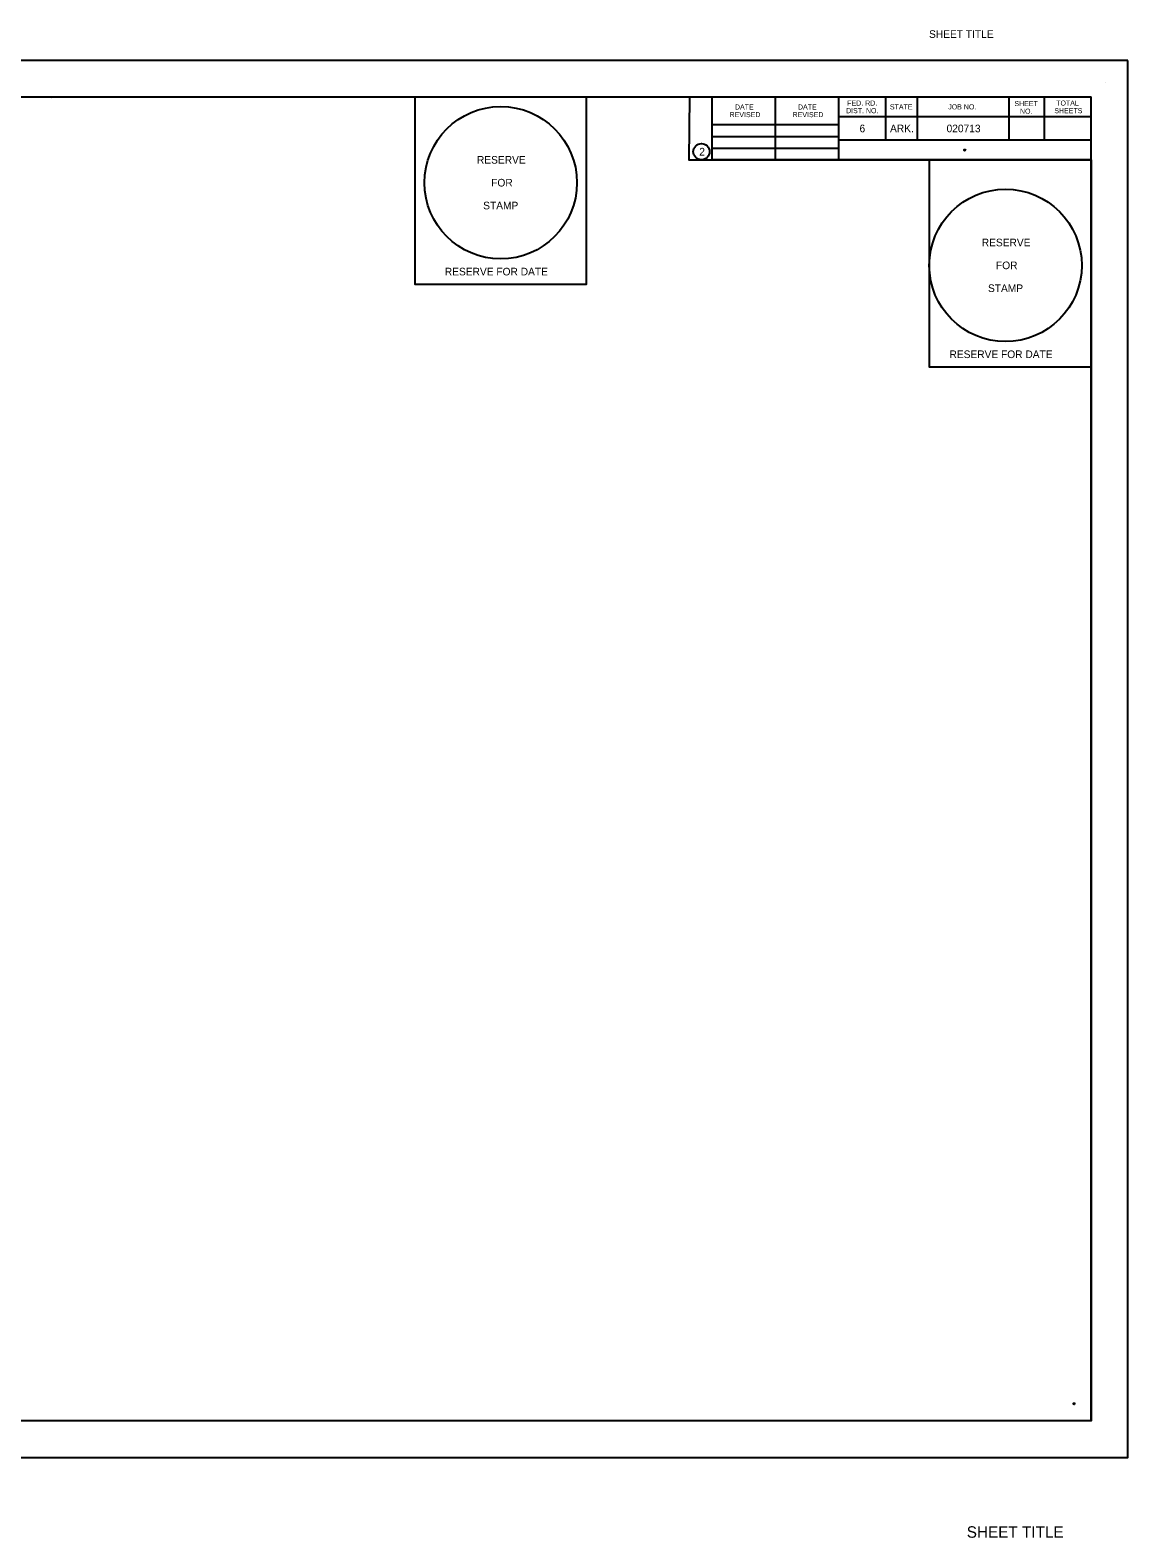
# Model space of a CAD drawing. Extents: x 0 to 17, y -0.6 to 11.2.
# Drawn here: x 8.36 to 17, y -0.63 to 11.24 of the extents above; entities that cross this region are included whole.
import ezdxf

# ---------------------------------------------------------------- set-up
doc = ezdxf.new("R2010")
doc.units = 0
for name, color, linetype in [('G-ANNO-TEXT', 7, 'Continuous'), ('G-Border-Paper', 7, 'Continuous'), ('G-Border-Sheet', 7, 'Continuous'), ('G-No Plot-Anchor', 7, 'Continuous'), ('G-No Plot-Border-1', 7, 'Continuous'), ('G-No Plot-Border-2', 7, 'Continuous'), ('G-No Plot-Stamp-1', 7, 'Continuous'), ('G-No Plot-Stamp-2', 7, 'Continuous'), ('G-Table-Major', 7, 'Continuous'), ('G-Table-Minor', 7, 'Continuous')]:
    doc.layers.add(name, color=color, linetype=linetype)

msp = doc.modelspace()

# ---------------------------------------------------------------- linework, layer by layer
at = {"layer": 'G-ANNO-TEXT'}
msp.add_line((16.821, 10.827), (16.821, 10.827), dxfattribs=at)
at = {"layer": 'G-Border-Paper'}
msp.add_lwpolyline([(17, 11), (0, 11), (0, 0), (17, 0)], close=True, dxfattribs=at)
at = {"layer": 'G-Border-Sheet'}
for p, q in [((0.758, 10.712), (16.712, 10.712)), ((16.712, 0.288), (16.712, 10.712)), ((16.712, 0.288), (0.758, 0.288))]:
    msp.add_line(p, q, dxfattribs=at)
at = {"layer": 'G-No Plot-Anchor'}
for centre in [(15.716, 10.294), (16.577, 0.423)]:
    msp.add_circle(centre, 0.005, dxfattribs=at)
at = {"layer": 'G-No Plot-Border-1'}
msp.add_lwpolyline([(0.758, 0.288), (0.758, 10.712), (12.738, 10.712), (12.738, 10.712), (12.738, 10.712), (13.548, 10.712), (13.545, 10.216), (14.721, 10.216), (16.712, 10.216), (15.437, 10.216), (15.437, 8.586), (16.712, 8.586), (16.712, 0.288)], close=True, dxfattribs=at)
at = {"layer": 'G-No Plot-Border-2'}
msp.add_lwpolyline([(0.758, 0.288), (0.758, 10.712), (11.388, 10.712), (11.388, 9.237), (12.738, 9.237), (12.738, 10.216), (12.738, 10.712), (13.548, 10.712), (13.545, 10.216), (14.721, 10.216), (14.721, 10.216), (16.712, 10.216), (16.712, 0.288)], close=True, dxfattribs=at)
at = {"layer": 'G-No Plot-Stamp-1'}
msp.add_circle((16.037, 9.386), 0.6, dxfattribs=at)
at = {"layer": 'G-No Plot-Stamp-2'}
msp.add_circle((12.063, 10.037), 0.6, dxfattribs=at)
at = {"layer": 'G-Table-Major'}
for p, q in [((13.728, 10.217), (13.728, 10.712)), ((14.721, 10.712), (14.721, 10.216)), ((13.728, 10.495), (14.721, 10.495)), ((16.712, 10.216), (13.728, 10.216))]:
    msp.add_line(p, q, dxfattribs=at)
msp.add_circle((13.643, 10.281), 0.0638, dxfattribs=at)
at = {"layer": 'G-Table-Minor'}
for p, q in [((8.529, 10.699), (8.529, 10.699)), ((8.529, 10.699), (8.529, 10.699)), ((14.226, 10.216), (14.226, 10.712)), ((15.093, 10.712), (15.093, 10.372)), ((15.341, 10.712), (15.341, 10.372)), ((16.062, 10.712), (16.062, 10.372)), ((16.34, 10.712), (16.34, 10.372)), ((16.712, 10.566), (16.712, 10.566)), ((16.712, 10.556), (14.721, 10.556)), ((13.728, 10.401), (14.721, 10.401)), ((16.712, 10.372), (14.721, 10.372)), ((13.728, 10.31), (14.721, 10.31))]:
    msp.add_line(p, q, dxfattribs=at)

# ---------------------------------------------------------------- texts
at = {"layer": 'G-ANNO-TEXT'}
for s, height, p in [('SHEET TITLE', 0.06, (15.435, 11.177)), ('TOTAL', 0.04, (16.436, 10.644)), ('REVISED', 0.04, (13.865, 10.553)), ('DATE', 0.04, (13.907, 10.613)), ('REVISED', 0.04, (14.361, 10.553)), ('DATE', 0.04, (14.403, 10.613)), ('DIST. NO.', 0.04, (14.782, 10.584)), ('FED. RD.', 0.04, (14.791, 10.644)), ('STATE', 0.04, (15.127, 10.614)), ('JOB NO.', 0.04, (15.586, 10.614)), ('SHEET', 0.04, (16.107, 10.64)), ('NO.', 0.04, (16.151, 10.58)), ('SHEETS', 0.04, (16.421, 10.584)), ('6', 0.06, (14.888, 10.434)), ('ARK.', 0.06, (15.128, 10.434)), ('020713', 0.06, (15.573, 10.434)), ('2', 0.06, (13.626, 10.251)), ('SHEET TITLE', 0.09, (15.732, -0.632))]:
    msp.add_text(s, height=height, dxfattribs=at).set_placement(p)
at = {"layer": 'G-No Plot-Stamp-1'}
for s, p in [('RESERVE', (15.85, 9.536)), ('FOR ', (15.962, 9.356)), ('STAMP', (15.899, 9.176)), ('RESERVE FOR DATE', (15.596, 8.656))]:
    msp.add_text(s, height=0.06, dxfattribs=at).set_placement(p)
at = {"layer": 'G-No Plot-Stamp-2'}
for s, p in [('RESERVE', (11.876, 10.187)), ('FOR ', (11.988, 10.007)), ('STAMP', (11.925, 9.827)), ('RESERVE FOR DATE', (11.623, 9.307))]:
    msp.add_text(s, height=0.06, dxfattribs=at).set_placement(p)

doc.saveas('drawing.dxf')
